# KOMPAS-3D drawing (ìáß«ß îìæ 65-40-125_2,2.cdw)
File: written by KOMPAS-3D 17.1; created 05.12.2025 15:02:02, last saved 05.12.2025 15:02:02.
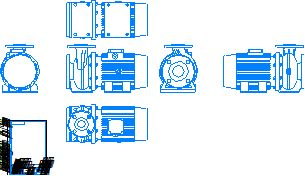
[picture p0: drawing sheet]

Sheet 1: A4, portrait

Title block, sheet 1: name: Насос МНС / 65-40-125_2,2; material: Сталь 10  ГОСТ 1050-88; mass: 80,68; sheets: 1; sheet format: A4

Views: Проекционный вид 2, Проекционный вид 3, Проекционный вид 4, Проекционный вид 5, Проекционный вид 6
Referenced files in \\adlc.lan\data\АДЛ_ПКД\3D-модели\ADL production\Насосы ГРАНПАМП\Насосы ГРАНПАМП серии МНС\KOMPAS 3D\: Насос МНС 65-40-125_2,2.m3d
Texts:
  Andrey
  АДЛ
Dimensions and other numbers on the sheet: 1:1; 1; 65-40-125_2,2; 80,68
